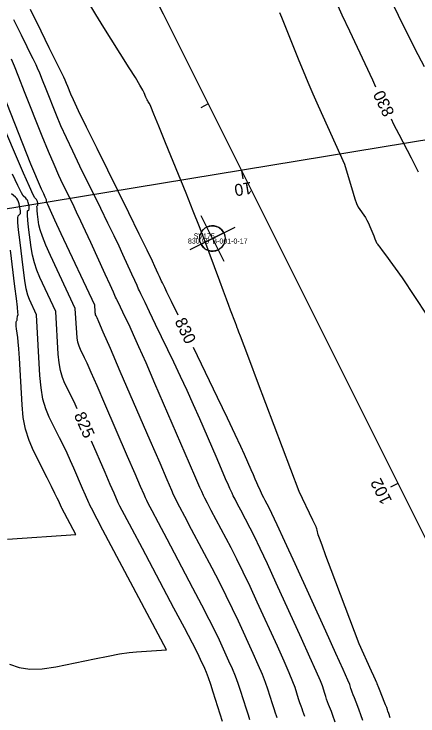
# Model space of a CAD drawing. Extents: x 1715724 to 1716561, y 394063 to 395906.
# Drawn here: x 1716231.8 to 1716279.5, y 394602.7 to 394685.4 of the extents above; entities that cross this region are included whole.
import ezdxf

# ---------------------------------------------------------------- set-up
doc = ezdxf.new("R2010")
doc.units = 0
for name, color, linetype in [('DT_X_Contour_Major', 7, 'Continuous'), ('DT_X_Contour_Minor', 7, 'Continuous'), ('GE_P_CL_10', 7, 'Continuous'), ('GT_Project_Soil_Boring', 7, 'Continuous'), ('SV_X_Text_Comment', 7, 'Continuous'), ('SV_X_Text_Elevation', 7, 'Continuous'), ('SV_X_Text_Name', 7, 'Continuous')]:
    doc.layers.add(name, color=color, linetype=linetype)

msp = doc.modelspace()

# ---------------------------------------------------------------- linework, layer by layer
at = {"layer": 'DT_X_Contour_Major'}
for points in [[(1716269.869, 394686.746), (1716270.516, 394685.364), (1716271.407, 394683.462), (1716274.109, 394677.7), (1716274.495, 394676.882)], [(1716251.193, 394649.949), (1716250.416, 394651.561), (1716249.869, 394652.697), (1716249.62, 394653.214), (1716249.353, 394653.768), (1716249.247, 394653.99), (1716248.998, 394654.523), (1716248.856, 394654.833), (1716248.461, 394655.7), (1716248.156, 394656.339), (1716247.538, 394657.608), (1716246.607, 394659.505), (1716245.363, 394662.03), (1716241.629, 394669.604), (1716240.386, 394672.133), (1716239.458, 394674.04), (1716238.845, 394675.324), (1716238.547, 394675.986), (1716238.174, 394676.921), (1716238.027, 394677.277), (1716237.866, 394677.642), (1716237.693, 394678.017), (1716237.506, 394678.402), (1716236.644, 394680.141), (1716235.991, 394681.463), (1716235.034, 394683.408), (1716233.77, 394685.974)], [(1716276.312, 394673.095), (1716276.619, 394672.469), (1716277.22, 394671.282), (1716278.667, 394668.488), (1716279.151, 394667.551), (1716279.518, 394666.836)], [(1716239.294, 394638.945), (1716239.051, 394639.472), (1716238.682, 394640.232), (1716237.823, 394641.935), (1716237.534, 394642.628), (1716237.31, 394643.431), (1716237.152, 394644.343), (1716237.059, 394645.365), (1716236.779, 394650.391), (1716234.894, 394654.405), (1716234.526, 394655.271), (1716234.232, 394656.148), (1716234.01, 394657.036), (1716233.861, 394657.936), (1716233.561, 394660.35), (1716233.469, 394661.149), (1716233.418, 394661.733), (1716233.407, 394662.104), (1716233.438, 394662.26), (1716233.573, 394662.393), (1716233.613, 394662.456), (1716233.632, 394662.547), (1716233.629, 394662.666), (1716233.606, 394662.812), (1716233.514, 394663.238), (1716233.47, 394663.39), (1716233.406, 394663.527), (1716233.322, 394663.649), (1716233.218, 394663.755), (1716232.914, 394664.02), (1716232.699, 394664.372), (1716232.283, 394665.23), (1716231.667, 394666.596)], [(1716272.976, 394602.198), (1716272.752, 394602.875), (1716272.557, 394603.433), (1716272.391, 394603.873), (1716271.989, 394604.889), (1716271.85, 394605.244), (1716271.735, 394605.547), (1716271.644, 394605.799), (1716271.576, 394605.998), (1716271.429, 394606.462), (1716271.211, 394606.985), (1716270.669, 394608.207), (1716269.801, 394610.127), (1716268.608, 394612.746), (1716264.993, 394620.661), (1716263.786, 394623.299), (1716262.874, 394625.277), (1716262.257, 394626.594), (1716261.937, 394627.25), (1716261.475, 394628.12), (1716261.31, 394628.436), (1716261.16, 394628.733), (1716261.025, 394629.009), (1716260.906, 394629.266), (1716260.608, 394629.923), (1716260.474, 394630.223), (1716260.295, 394630.63), (1716260.071, 394631.144), (1716259.801, 394631.765), (1716259.023, 394633.562), (1716258.607, 394634.488), (1716257.939, 394635.915), (1716257.022, 394637.845), (1716255.854, 394640.277), (1716253.016, 394646.166)], [(1716256.434, 394602.083), (1716256.16, 394602.944), (1716255.328, 394605.563), (1716255.032, 394606.473), (1716254.768, 394607.238), (1716254.535, 394607.859), (1716254.335, 394608.334), (1716253.844, 394609.41), (1716253.509, 394610.091), (1716252.872, 394611.328), (1716251.933, 394613.119), (1716250.693, 394615.467), (1716246.982, 394622.467), (1716245.76, 394624.773), (1716244.878, 394626.442), (1716244.335, 394627.474), (1716244.13, 394627.869), (1716244.039, 394628.072), (1716243.921, 394628.339), (1716243.639, 394628.991), (1716243.19, 394630.025), (1716242.576, 394631.443), (1716240.992, 394635.104)]]:
    msp.add_lwpolyline(points, dxfattribs=at)
at = {"layer": 'DT_X_Contour_Minor'}
for points in [[(1716276.222, 394602.522), (1716276.032, 394603.032), (1716275.938, 394603.331), (1716275.884, 394603.486), (1716275.795, 394603.727), (1716275.669, 394604.053), (1716275.507, 394604.464), (1716275.027, 394605.676), (1716274.869, 394606.075), (1716274.686, 394606.542), (1716274.66, 394606.609), (1716274.649, 394606.642), (1716274.607, 394606.738), (1716274.487, 394607.002), (1716274.29, 394607.435), (1716274.016, 394608.035), (1716272.557, 394611.231), (1716269.256, 394619.959), (1716268.63, 394621.621), (1716268.167, 394622.863), (1716267.868, 394623.688), (1716267.732, 394624.094), (1716267.587, 394624.619), (1716267.538, 394624.794), (1716267.502, 394624.924), (1716267.477, 394625.01), (1716267.464, 394625.05), (1716267.446, 394625.099), (1716267.404, 394625.191), (1716267.289, 394625.431), (1716267.103, 394625.818), (1716265.476, 394629.188), (1716260.574, 394642.141), (1716259.649, 394644.586), (1716258.973, 394646.372), (1716258.548, 394647.497), (1716258.373, 394647.962), (1716258.239, 394648.322), (1716258.175, 394648.493), (1716258.084, 394648.737), (1716257.965, 394649.053), (1716257.39, 394650.573), (1716257.191, 394651.103), (1716256.914, 394651.844), (1716256.56, 394652.795), (1716256.128, 394653.958), (1716254.873, 394657.34), (1716254.349, 394658.728), (1716253.716, 394660.355), (1716252.976, 394662.222), (1716252.127, 394664.329), (1716249.72, 394670.265), (1716248.924, 394672.224), (1716248.339, 394673.647), (1716247.967, 394674.535), (1716247.807, 394674.888), (1716247.663, 394675.114), (1716247.606, 394675.211), (1716247.544, 394675.335), (1716247.475, 394675.485), (1716247.401, 394675.66), (1716247.197, 394676.163), (1716247.029, 394676.487), (1716246.679, 394677.083), (1716246.147, 394677.951), (1716245.433, 394679.091), (1716243.287, 394682.493), (1716242.436, 394683.855), (1716241.491, 394685.392), (1716240.453, 394687.102)], [(1716276.183, 394687.363), (1716277.149, 394685.304), (1716277.611, 394684.347), (1716278.273, 394683.022), (1716279.136, 394681.329), (1716280.198, 394679.267)], [(1716263.16, 394685.622), (1716263.368, 394685.092), (1716263.688, 394684.289), (1716265.418, 394679.982), (1716265.927, 394678.738), (1716266.48, 394677.43), (1716267.077, 394676.057), (1716267.718, 394674.621), (1716270.811, 394667.769), (1716271.825, 394664.359), (1716272.038, 394663.688), (1716272.243, 394663.138), (1716272.439, 394662.709), (1716272.626, 394662.4), (1716273.114, 394661.737), (1716273.296, 394661.468), (1716273.473, 394661.158), (1716273.647, 394660.808), (1716273.817, 394660.416), (1716274.266, 394659.319), (1716274.417, 394658.954), (1716274.532, 394658.682), (1716274.613, 394658.503), (1716274.658, 394658.418), (1716274.732, 394658.316), (1716274.81, 394658.209), (1716274.986, 394657.968), (1716275.262, 394657.591), (1716275.638, 394657.079), (1716277.621, 394654.372), (1716281.977, 394647.76)], [(1716269.709, 394602.022), (1716269.444, 394602.813), (1716269.275, 394603.281), (1716268.95, 394604.101), (1716268.83, 394604.413), (1716268.714, 394604.731), (1716268.602, 394605.056), (1716268.493, 394605.388), (1716268.209, 394606.282), (1716267.975, 394606.883), (1716267.488, 394608.013), (1716266.748, 394609.673), (1716265.753, 394611.864), (1716262.763, 394618.411), (1716261.73, 394620.658), (1716260.873, 394622.487), (1716260.192, 394623.899), (1716259.688, 394624.893), (1716258.577, 394626.989), (1716258.2, 394627.704), (1716257.904, 394628.275), (1716257.687, 394628.702), (1716257.551, 394628.986), (1716257.294, 394629.553), (1716257.12, 394629.947), (1716256.79, 394630.704), (1716256.303, 394631.825), (1716255.661, 394633.308), (1716253.739, 394637.749), (1716253.008, 394639.415), (1716252.255, 394641.083), (1716251.481, 394642.752), (1716250.686, 394644.423), (1716248.538, 394648.881), (1716247.825, 394650.36), (1716247.299, 394651.453), (1716246.957, 394652.161), (1716246.802, 394652.483), (1716246.636, 394652.828), (1716246.532, 394653.049), (1716246.346, 394653.453), (1716246.077, 394654.04), (1716245.726, 394654.809), (1716244.678, 394657.106), (1716244.219, 394658.092), (1716243.63, 394659.328), (1716242.909, 394660.814), (1716242.058, 394662.548), (1716239.612, 394667.508), (1716238.752, 394669.279), (1716238.007, 394670.873), (1716237.375, 394672.29), (1716236.858, 394673.53), (1716235.631, 394676.601), (1716235.211, 394677.643), (1716234.873, 394678.465), (1716234.615, 394679.067), (1716234.439, 394679.45), (1716234.077, 394680.178), (1716233.834, 394680.669), (1716233.377, 394681.596), (1716232.706, 394682.959), (1716231.82, 394684.758)], [(1716266.159, 394602.689), (1716265.912, 394603.314), (1716265.811, 394603.581), (1716265.693, 394603.914), (1716265.56, 394604.312), (1716265.41, 394604.777), (1716264.989, 394606.102), (1716264.74, 394606.78), (1716264.308, 394607.819), (1716263.695, 394609.22), (1716262.899, 394610.981), (1716260.534, 394616.161), (1716259.675, 394618.016), (1716258.873, 394619.697), (1716258.128, 394621.204), (1716257.439, 394622.537), (1716255.678, 394625.859), (1716255.09, 394626.971), (1716254.647, 394627.817), (1716254.349, 394628.395), (1716254.196, 394628.707), (1716253.98, 394629.183), (1716253.766, 394629.671), (1716253.284, 394630.778), (1716252.536, 394632.505), (1716251.52, 394634.852), (1716248.454, 394641.936), (1716247.409, 394644.343), (1716246.571, 394646.251), (1716245.941, 394647.659), (1716245.519, 394648.569), (1716244.67, 394650.33), (1716244.389, 394650.914), (1716244.181, 394651.346), (1716244.046, 394651.625), (1716243.985, 394651.752), (1716243.919, 394651.889), (1716243.818, 394652.108), (1716243.563, 394652.664), (1716243.156, 394653.557), (1716242.595, 394654.786), (1716240.895, 394658.513), (1716240.283, 394659.845), (1716239.722, 394661.049), (1716239.212, 394662.122), (1716238.752, 394663.067), (1716237.596, 394665.412), (1716237.119, 394666.425), (1716236.556, 394667.707), (1716235.905, 394669.257), (1716235.169, 394671.075), (1716233.088, 394676.28), (1716232.396, 394678.008), (1716231.879, 394679.287), (1716231.538, 394680.117)], [(1716262.873, 394602.527), (1716262.791, 394602.75), (1716262.673, 394603.097), (1716262.518, 394603.569), (1716262.327, 394604.166), (1716261.768, 394605.923), (1716261.504, 394606.678), (1716261.128, 394607.626), (1716260.642, 394608.766), (1716260.044, 394610.099), (1716258.304, 394613.91), (1716257.62, 394615.374), (1716256.873, 394616.907), (1716256.063, 394618.509), (1716255.19, 394620.18), (1716252.779, 394624.728), (1716251.98, 394626.238), (1716251.391, 394627.358), (1716251.011, 394628.088), (1716250.841, 394628.428), (1716250.666, 394628.812), (1716250.444, 394629.32), (1716249.908, 394630.555), (1716249.058, 394632.517), (1716247.894, 394635.206), (1716244.371, 394643.347), (1716243.209, 394646.03), (1716242.365, 394647.973), (1716241.84, 394649.177), (1716241.633, 394649.641), (1716241.506, 394649.893), (1716241.464, 394649.996), (1716241.43, 394650.115), (1716241.407, 394650.25), (1716241.393, 394650.401), (1716241.352, 394651.144), (1716237.399, 394659.561), (1716236.657, 394661.145), (1716236.125, 394662.289), (1716235.804, 394662.993), (1716235.693, 394663.257), (1716235.679, 394663.375), (1716235.674, 394663.415), (1716235.672, 394663.443), (1716235.671, 394663.461), (1716235.673, 394663.469), (1716235.679, 394663.475), (1716235.681, 394663.479), (1716235.682, 394663.483), (1716235.682, 394663.489), (1716235.681, 394663.496), (1716235.676, 394663.517), (1716235.674, 394663.524), (1716235.671, 394663.531), (1716235.667, 394663.537), (1716235.662, 394663.542), (1716235.647, 394663.555), (1716235.608, 394663.638), (1716235.503, 394663.877), (1716235.331, 394664.272), (1716235.092, 394664.823), (1716233.823, 394667.758), (1716229.989, 394677.353)], [(1716259.652, 394602.281), (1716259.476, 394602.826), (1716259.243, 394603.555), (1716258.548, 394605.743), (1716258.268, 394606.575), (1716257.948, 394607.432), (1716257.588, 394608.312), (1716257.19, 394609.217), (1716256.074, 394611.66), (1716255.564, 394612.733), (1716254.872, 394614.117), (1716253.998, 394615.814), (1716252.941, 394617.823), (1716249.881, 394623.597), (1716248.87, 394625.506), (1716248.134, 394626.9), (1716247.673, 394627.781), (1716247.486, 394628.148), (1716247.353, 394628.442), (1716247.183, 394628.83), (1716246.773, 394629.773), (1716246.124, 394631.271), (1716245.235, 394633.325), (1716242.545, 394639.541), (1716241.639, 394641.627), (1716240.939, 394643.221), (1716240.445, 394644.325), (1716240.158, 394644.937), (1716239.665, 394645.914), (1716239.499, 394646.312), (1716239.37, 394646.773), (1716239.28, 394647.296), (1716239.226, 394647.883), (1716239.066, 394650.768), (1716236.146, 394656.983), (1716235.592, 394658.208), (1716235.178, 394659.218), (1716234.907, 394660.015), (1716234.777, 394660.597), (1716234.62, 394661.863), (1716234.572, 394662.282), (1716234.545, 394662.588), (1716234.539, 394662.782), (1716234.555, 394662.865), (1716234.626, 394662.934), (1716234.647, 394662.967), (1716234.657, 394663.015), (1716234.656, 394663.077), (1716234.643, 394663.154), (1716234.595, 394663.377), (1716234.572, 394663.457), (1716234.538, 394663.529), (1716234.494, 394663.593), (1716234.44, 394663.649), (1716234.28, 394663.787), (1716234.093, 394664.144), (1716233.652, 394665.112), (1716232.956, 394666.689), (1716232.005, 394668.877), (1716229.132, 394675.526)], [(1716231.316, 394608.842), (1716232.421, 394608.441), (1716233.699, 394608.257), (1716235.15, 394608.29), (1716236.775, 394608.539), (1716241.34, 394609.492), (1716242.932, 394609.811), (1716244.285, 394610.053), (1716245.4, 394610.218), (1716246.276, 394610.307), (1716249.807, 394610.539), (1716242.329, 394624.648), (1716240.961, 394627.235), (1716240.775, 394627.589), (1716240.725, 394627.701), (1716240.66, 394627.849), (1716240.257, 394628.779), (1716239.918, 394629.562), (1716238.893, 394631.93), (1716238.499, 394632.821), (1716238.087, 394633.718), (1716237.656, 394634.62), (1716237.206, 394635.527), (1716235.982, 394637.955), (1716235.569, 394638.944), (1716235.25, 394640.089), (1716235.025, 394641.39), (1716234.892, 394642.848), (1716234.493, 394650.014), (1716233.642, 394651.827), (1716233.461, 394652.334), (1716233.285, 394653.078), (1716233.113, 394654.058), (1716232.945, 394655.276), (1716232.502, 394658.838), (1716232.367, 394660.016), (1716232.291, 394660.878), (1716232.275, 394661.425), (1716232.32, 394661.656), (1716232.52, 394661.851), (1716232.579, 394661.945), (1716232.607, 394662.079), (1716232.603, 394662.254), (1716232.568, 394662.47), (1716232.433, 394663.098), (1716232.368, 394663.323), (1716232.273, 394663.525), (1716232.149, 394663.705), (1716231.996, 394663.862), (1716231.547, 394664.252)], [(1716231.063, 394623.581), (1716239.115, 394624.111), (1716237.455, 394627.243), (1716237.42, 394627.31), (1716237.067, 394628.124), (1716236.929, 394628.418), (1716236.661, 394628.966), (1716236.261, 394629.767), (1716235.73, 394630.823), (1716234.14, 394633.976), (1716233.608, 394635.203), (1716233.203, 394636.518), (1716232.926, 394637.921), (1716232.776, 394639.414), (1716232.548, 394643.511), (1716232.467, 394644.902), (1716232.395, 394646.004), (1716232.331, 394646.816), (1716232.277, 394647.338), (1716232.143, 394648.343), (1716232.102, 394648.679), (1716232.081, 394648.933), (1716232.079, 394649.104), (1716232.095, 394649.193), (1716232.166, 394649.321), (1716232.189, 394649.371), (1716232.206, 394649.425), (1716232.217, 394649.483), (1716232.222, 394649.546), (1716232.228, 394649.848), (1716232.306, 394650.036), (1716232.296, 394650.272), (1716232.231, 394650.902), (1716232.112, 394651.924), (1716231.939, 394653.339), (1716231.405, 394657.635)]]:
    msp.add_lwpolyline(points, dxfattribs=at)
at = {"layer": 'GE_P_CL_10'}
for p, q in [((1716249.46, 394685.42), (1715852.538, 395456.564)), ((1716447.809, 394289.082), (1716249.46, 394685.42)), ((1716306.2, 394674.833), (1716217.392, 394660.231)), ((1716254.746, 394674.859), (1716253.852, 394674.412)), ((1716258.67, 394667.018), (1716258.832, 394666.031)), ((1716277.123, 394630.146), (1716276.228, 394629.698))]:
    msp.add_line(p, q, dxfattribs=at)
at = {"layer": 'GT_Project_Soil_Boring'}
for p, q in [((1716255.239, 394658.999), (1716253.897, 394661.681)), ((1716255.239, 394658.999), (1716254.568, 394660.34)), ((1716255.239, 394658.999), (1716257.922, 394660.341)), ((1716255.239, 394658.999), (1716252.556, 394657.656)), ((1716253.898, 394658.327), (1716255.239, 394658.999)), ((1716256.581, 394659.67), (1716255.239, 394658.999)), ((1716255.239, 394658.999), (1716256.582, 394656.316)), ((1716255.239, 394658.999), (1716255.911, 394657.657))]:
    msp.add_line(p, q, dxfattribs=at)
msp.add_circle((1716255.239, 394658.999), 1.5, dxfattribs=at)
for start, end in [(26.58573, 116.58573), (206.58573, 296.58573)]:
    msp.add_arc((1716255.239, 394658.999), 1.5, start, end, dxfattribs=at)

# ---------------------------------------------------------------- texts
at = {"layer": 'DT_X_Contour_Major'}
for s, rotation, p in [('830', 115.63072, (1716276.747, 394673.787)), ('830', 295.72936, (1716250.751, 394649.253)), ('825', 293.85581, (1716238.874, 394638.193))]:
    msp.add_text(s, height=1.4, rotation=rotation, dxfattribs=at).set_placement(p)
at = {"layer": 'GE_P_CL_10'}
for s, rotation, p in [('10', 189.33738, (1716259.789, 394665.682)), ('102', 116.58573, (1716276.464, 394628.11))]:
    msp.add_text(s, height=1.4, rotation=rotation, dxfattribs=at).set_placement(p)
at = {"layer": 'SV_X_Text_Comment'}
msp.add_text('B-001-0-17', height=0.6, dxfattribs=at).set_placement((1716255.239, 394658.399))
at = {"layer": 'SV_X_Text_Elevation'}
msp.add_text('830.99', height=0.6, dxfattribs=at).set_placement((1716252.348, 394658.399))
at = {"layer": 'SV_X_Text_Name'}
msp.add_text('SV175', height=0.6, dxfattribs=at).set_placement((1716253.029, 394658.999))

doc.saveas('drawing.dxf')
